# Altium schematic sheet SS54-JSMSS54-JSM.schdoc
size 127 x 101 mm
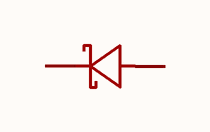
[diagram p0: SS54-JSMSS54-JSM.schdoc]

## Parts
D?  ss54-jsm  [SMB_L4.4-W3.6-LS5.3-RD]  (value not drawn)

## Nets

Not connected (* = marked no-connect by the designer): D? 1(C) 2(A)

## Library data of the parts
D? = ss54-jsm: 二极管配置:独立式;正向压降(Vf):550mV@5A;直流反向耐压(Vr):40V;整流电流:5A;; Manufacturer: JSMSEMI(杰盛微); AddInBom: yes; ModelId: 2e2b5067ebdf4b2391651ce058af3163; ModelTransform: 208.661,142.5194,0,0,0,0,0,0,0; Diode Configuration: 独立式; Voltage - DC Reverse(Vr): 40V; Current - Rectified: 5A; Reverse Leakage Current (Ir): 100uA@40V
